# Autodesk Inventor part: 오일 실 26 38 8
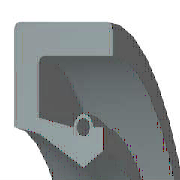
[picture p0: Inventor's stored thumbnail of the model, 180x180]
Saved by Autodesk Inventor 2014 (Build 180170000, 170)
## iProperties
IsCustomPart: 1
Created: 2012-02
Part Number: 오일 실 26 38 8
Material: 고무
Description: 오일-실
Document SubType Name: Modeling
Standard: KS B 2804
Designer: mduedu
Standards Organization: KS
Language: ko-KR
Size Designation: S - 26 38 8
Categories: <MemberInstance><Categories><Category DisplayName="샤프트 부품" InternalName="7f7aeb1f-a693-4053-b835-cee3144e0d98" Mnemonic="SHFT"><Category DisplayName="실링" Intern
Density: 0.93 g/cm^3
Appearance: 고무 - 검은색 - 버전 1.1
Author: mduedu
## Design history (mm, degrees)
revolve "본체" stored, may be unused: angle "d17" = 90 deg
revolve "스프링1" stored, may be unused: angle "d18" = 90 deg
body "Solid1"
sketch "스케치1"
  geometry: L1 (0, 19)-(8, 19); L2 (8, 19)-(8, 17.75); L3 (8, 17.75)-(1.75, 17.75); L4 (0, 19)-(0, 15.1); L5 (0, 15.1)-(1.75, 14.75); L6 (1.75, 14.75)-(4.9, 13); L7 (4.9, 13)-(0, 13); L8 (6.3, 13.875)-(6.3, 15.1); L9 (0, 0)-(9.586, 0) reference; L10 (4.9, 13)-(6.3, 13.875); L11 (0, 18)-(0, -3) reference; L12 (-1.917, 0)-(11.503, 0) reference; L13 (4.2, 15.1)-(1.75, 15.59); L14 (1.75, 15.59)-(1.75, 17.75); L15 (6.3, 15.1)-(5.6, 15.1); C1 r 0.455 at (4.9, 15.1); A1 r 0.7 centre (4.9, 15.1) between (5.6, 15.1) and (4.2, 15.1)
  constraints: 26 end point, 5 horizontal alignment, 4 perpendicular, 2 centre point, 2 collinear, 2 horizontal, 2 parallel, 2 point on circle, 2 point on line, 2 vertical alignment, 1 coincident
  dimensions: "d0" = 38 diameter of L1 L9 (= SD2); "d1" = 27.75 diameter of L8.start L9 (= ABDM); "d2" = 1.25 distance of L1.end L2.end (computed from SD); "d3" = 0.91 diameter of C1 (= SPDI); "d4" = 1.4 diameter of A1 (= SPDA); "d5" = 26 diameter of L6.end L9 (= NND); "d6" = 29.5 diameter of L5.end L9 (= TKDM); "d7" = 30.2 diameter of L4.end L9 (= HLDM); "d8" = 4.9 distance from line of C1.centre L4 (= SPDST); "d9" = 6.3 distance between parallel lines of L8 L4 (= SDI); "d10" = 8 distance between parallel lines of L2 L4 (= SWDT); "d12" = 1.75 distance between parallel lines of L14 L4 (= SD)
fillet "모깎기1" dims "d11" = 0.3 (= RR)
other parameters: "SD2" = 38 [user parameter; used in 1 equation term], "SWDT" = 8 [user parameter; used in 1 equation term], "RR" = 0.3 [user parameter; used in 1 equation term], "SD" = 1.75 [user parameter; used in 2 equation terms], "NND" = 26 [user parameter; used in 1 equation term], "SPDA" = 1.4 [user parameter; used in 1 equation term], "SPDI" = 0.91 [user parameter; used in 1 equation term], "TKDM" = 29.5 [user parameter; used in 1 equation term], "HLDM" = 30.2 [user parameter; used in 1 equation term], "ABDM" = 27.75 [user parameter; used in 1 equation term], "SDI" = 6.3 [user parameter; used in 1 equation term], "SPDST" = 4.9 [user parameter; used in 1 equation term], "d13" = 0, "d14" = 0, "d15" = 0, "LAB" = 0.35 [user parameter]
